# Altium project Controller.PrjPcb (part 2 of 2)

## Sheet Auxiliary Power.SchDoc: 60KW GMA DAB (CONTROL) - AUXILIARY POWER
size 431 x 279 mm; Date: 11/2023; Revision: 1.0; SheetNumber: 5; SheetTotal: 5; SheetSize: B; DrawingNumber: CRD60DD12N-GMA-CONTROL
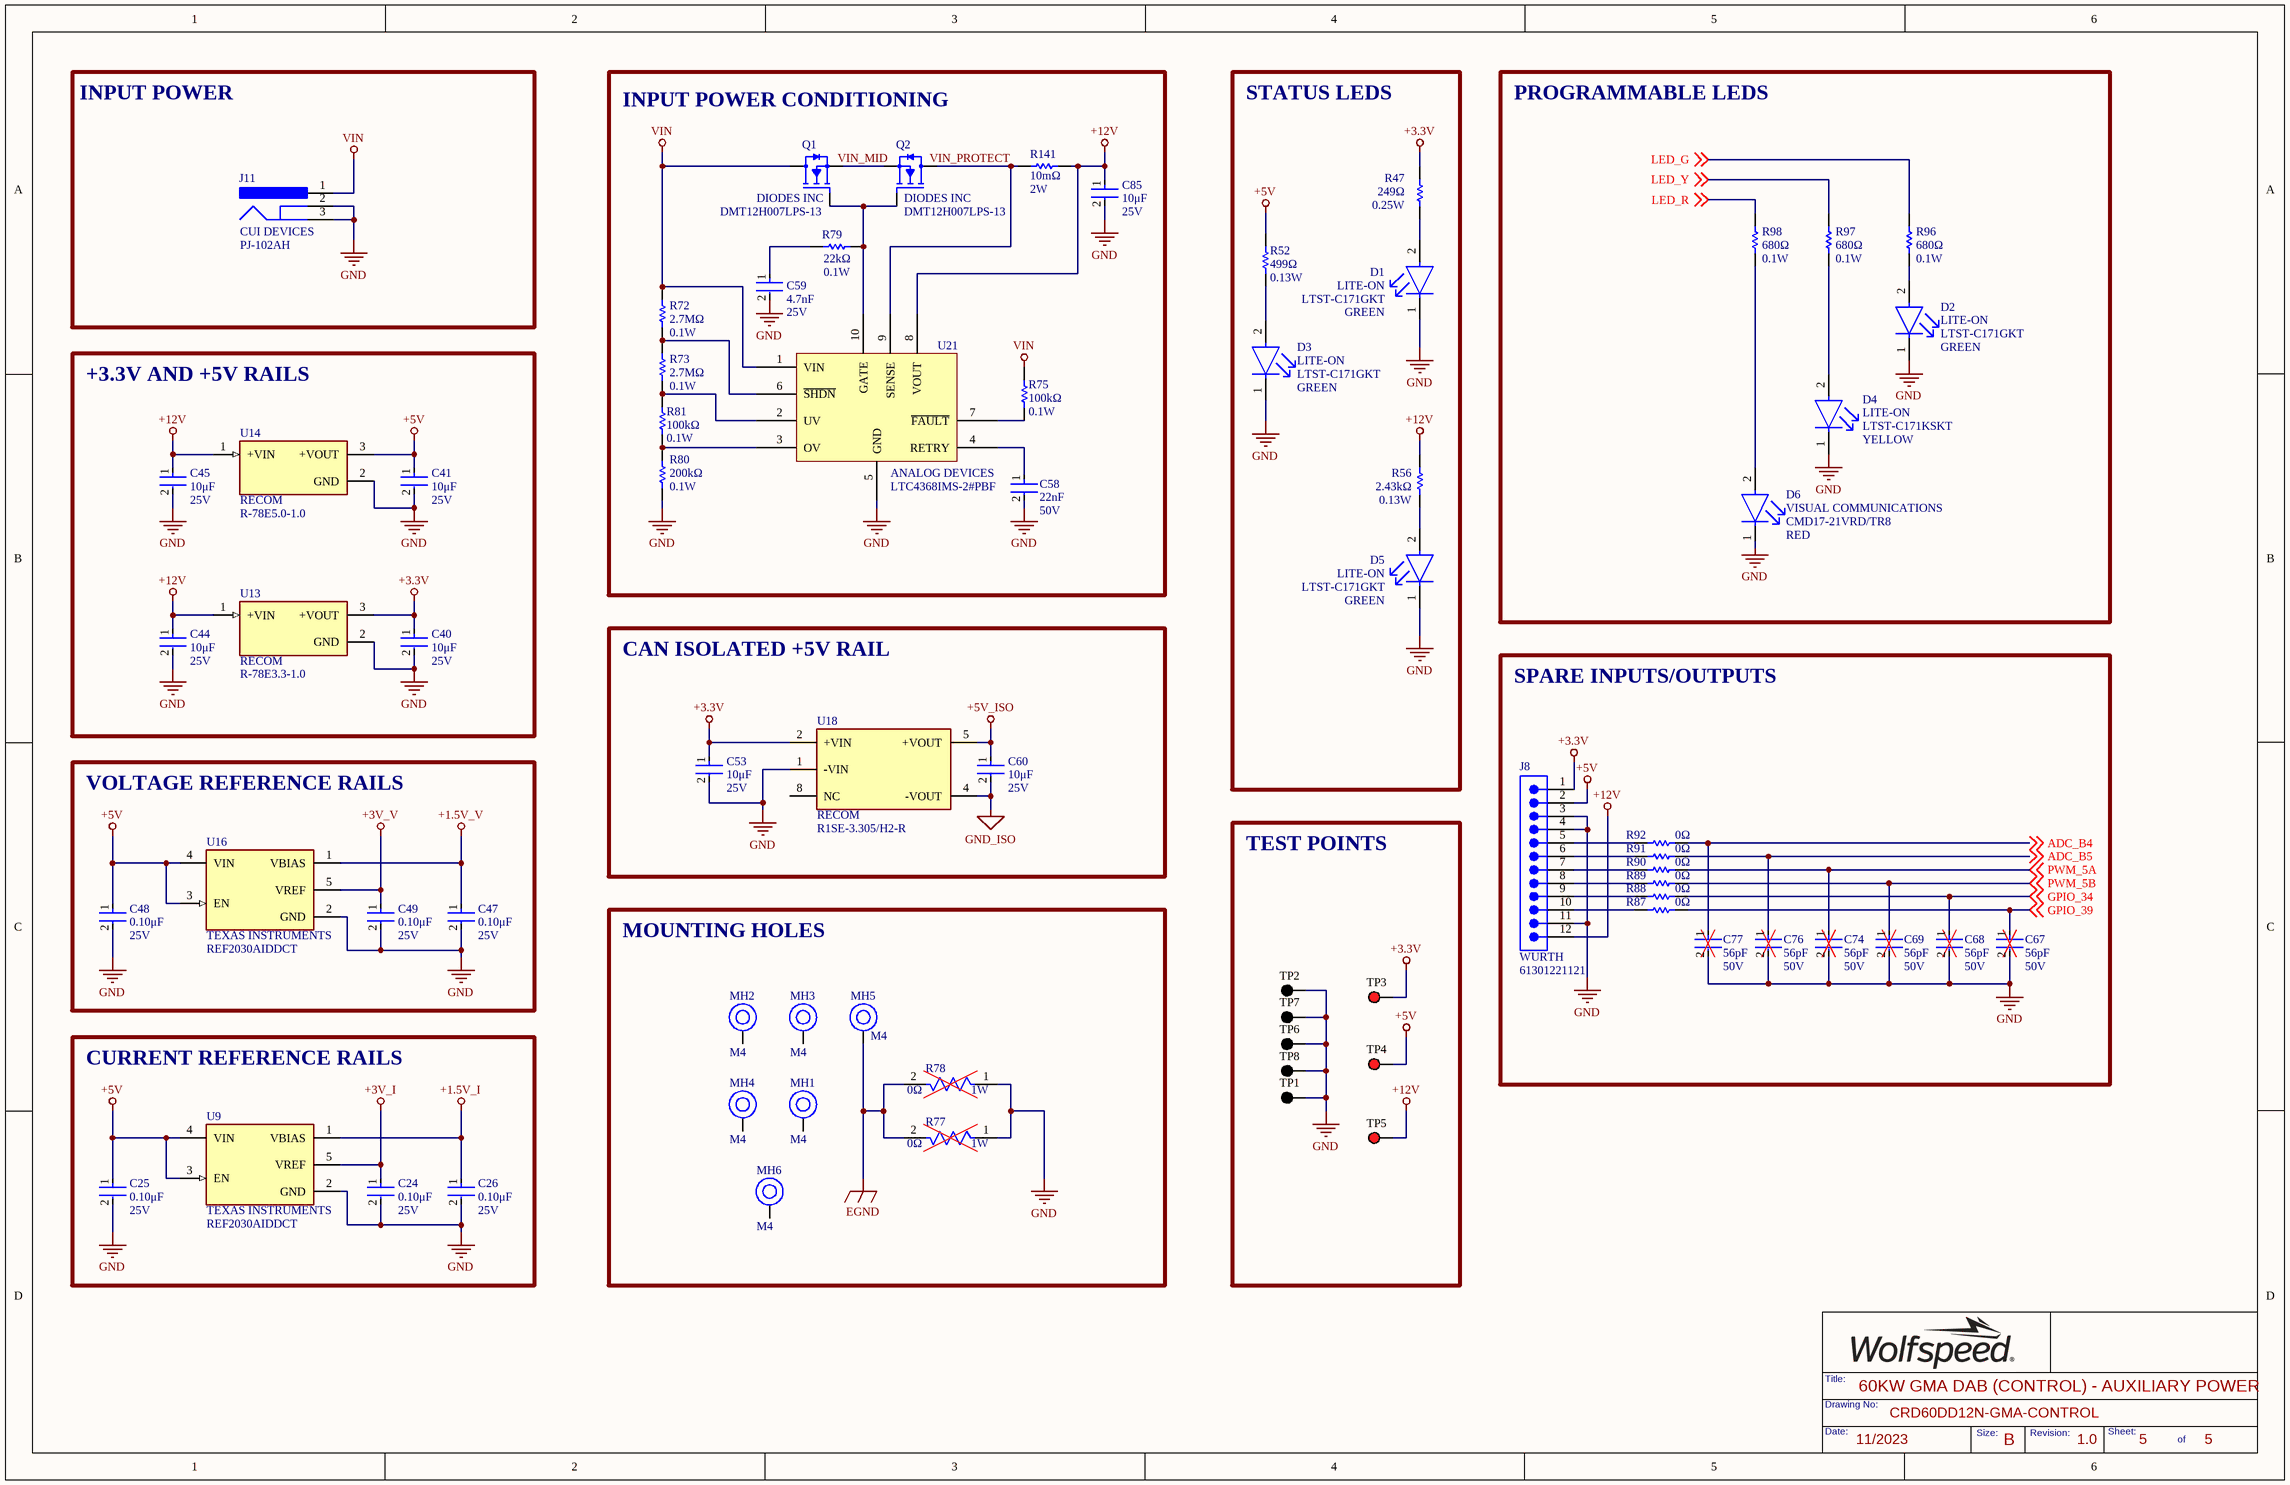
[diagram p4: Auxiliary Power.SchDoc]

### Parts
C24  Voltage Rating: 25V  Capacitance: 0.10μF  [FP-C0603C-CF-IPC_B]  (hidden comment: C0603C104K3RACTU)
C25  Voltage Rating: 25V  Capacitance: 0.10μF  [FP-C0603C-CF-IPC_B]  (hidden comment: C0603C104K3RACTU)
C26  Voltage Rating: 25V  Capacitance: 0.10μF  [FP-C0603C-CF-IPC_B]  (hidden comment: C0603C104K3RACTU)
C40  Voltage Rating: 25V  Capacitance: 10μF  [FP-CL31-IPC_B]  (hidden comment: CL31B106KAHSFNE)
C41  Voltage Rating: 25V  Capacitance: 10μF  [FP-CL31-IPC_B]  (hidden comment: CL31B106KAHSFNE)
C44  Voltage Rating: 25V  Capacitance: 10μF  [FP-CL31-IPC_B]  (hidden comment: CL31B106KAHSFNE)
C45  Voltage Rating: 25V  Capacitance: 10μF  [FP-CL31-IPC_B]  (hidden comment: CL31B106KAHSFNE)
C47  Voltage Rating: 25V  Capacitance: 0.10μF  [FP-C0603C-CF-IPC_B]  (hidden comment: C0603C104K3RACTU)
C48  Voltage Rating: 25V  Capacitance: 0.10μF  [FP-C0603C-CF-IPC_B]  (hidden comment: C0603C104K3RACTU)
C49  Voltage Rating: 25V  Capacitance: 0.10μF  [FP-C0603C-CF-IPC_B]  (hidden comment: C0603C104K3RACTU)
C53  Voltage Rating: 25V  Capacitance: 10μF  [FP-CL31-IPC_B]  (hidden comment: CL31B106KAHSFNE)
C58  Capacitance: 22nF  Voltage: 50V  [FP-C0603C-CF-IPC_B]  (hidden comment: CC0805KRX7R9BB223)
C59  Voltage Rating: 25V  Capacitance: 4.7nF  [FP-C0603C-CF-IPC_B]  (hidden comment: C0603C472K3RAC7867)
C60  Voltage Rating: 25V  Capacitance: 10μF  [FP-CL31-IPC_B]  (hidden comment: CL31B106KAHSFNE)
C67  Capacitance: 56pF  Voltage Rating: 50V  [FP-C0603C-CF-IPC_B]  (hidden comment: CL10C560JB8NNNC)
C68  Capacitance: 56pF  Voltage Rating: 50V  [FP-C0603C-CF-IPC_B]  (hidden comment: CL10C560JB8NNNC)
C69  Capacitance: 56pF  Voltage Rating: 50V  [FP-C0603C-CF-IPC_B]  (hidden comment: CL10C560JB8NNNC)
C74  Capacitance: 56pF  Voltage Rating: 50V  [FP-C0603C-CF-IPC_B]  (hidden comment: CL10C560JB8NNNC)
C76  Capacitance: 56pF  Voltage Rating: 50V  [FP-C0603C-CF-IPC_B]  (hidden comment: CL10C560JB8NNNC)
C77  Capacitance: 56pF  Voltage Rating: 50V  [FP-C0603C-CF-IPC_B]  (hidden comment: CL10C560JB8NNNC)
C85  Voltage Rating: 25V  Capacitance: 10μF  [FP-CL31-IPC_B]  (hidden comment: CL31B106KAHSFNE)
D1  value GREEN  Manufacturer: LITE-ON  [FP-LTST-C171GKT-MFG]  (hidden comment: LTST-C171GKT)
D2  value GREEN  Manufacturer: LITE-ON  [FP-LTST-C171GKT-MFG]  (hidden comment: LTST-C171GKT)
D3  value GREEN  Manufacturer: LITE-ON  [FP-LTST-C171GKT-MFG]  (hidden comment: LTST-C171GKT)
D4  LTST-C171KSKT  value YELLOW  Manufacturer: LITE-ON  [FP-LTST-C171GKT-MFG-YELLOW]
D5  value GREEN  Manufacturer: LITE-ON  [FP-LTST-C171GKT-MFG]  (hidden comment: LTST-C171GKT)
D6  value RED  Manufacturer: VISUAL COMMUNICATIONS  [FP-LTST-C171GKT-MFG-RED]  (hidden comment: CMD17-21VRD/TR8)
J8  Manufacturer Print: WURTH  [FP-61301221121-MFG]  (hidden comment: 61301221121)
J11  PJ-102AH  Manufacturer Print: CUI DEVICES  [CUI-PJ-102B_V]
MH1  Size: M4  [MH_M4_P]  (hidden comment: MH_M4_P)
MH2  Size: M4  [MH_M4_P]  (hidden comment: MH_M4_P)
MH3  Size: M4  [MH_M4_P]  (hidden comment: MH_M4_P)
MH4  Size: M4  [MH_M4_P]  (hidden comment: MH_M4_P)
MH5  Size: M4  [MH_M4_P]  (hidden comment: MH_M4_P)
MH6  Size: M4  [MH_M4_P]  (hidden comment: MH_M4_P)
Q1  DMT12H007LPS-13  Manufacturer: DIODES INC  [FP-PowerDI5060-8-MFG]
Q2  DMT12H007LPS-13  Manufacturer: DIODES INC  [FP-PowerDI5060-8-MFG]
R47  Resistance: 249Ω  Power Rating: 0.25W  [FP-MCR18-IPC_A]  (hidden comment: RC1206FR-07249RL)
R52  Resistance: 499Ω  Max Power Dissipation: 0.13W  [FP-MCR10-IPC_A]  (hidden comment: RC0805FR-07499RL)
R56  Resistance: 2.43kΩ  Power Rating: 0.13W  [FP-MCR10-IPC_A]  (hidden comment: ERJ-6ENF2431V)
R72  Power Rating: 0.1W  Resistance: 2.7MΩ  [FP-MCR03-IPC_B]  (hidden comment: RC0603JR-072M7L)
R73  Power Rating: 0.1W  Resistance: 2.7MΩ  [FP-MCR03-IPC_B]  (hidden comment: RC0603JR-072M7L)
R75  Resistance: 100kΩ  Power Rating: 0.1W  [FP-MCR03-IPC_B]  (hidden comment: RC0603FR-07100KL)
R77  value 0Ω  Max Power Dissipation: 1W  [FP-RC2512-0_65-IPC_C]  (hidden comment: RC2512JK-070RL)
R78  value 0Ω  Max Power Dissipation: 1W  [FP-RC2512-0_65-IPC_C]  (hidden comment: RC2512JK-070RL)
R79  Power Rating: 0.1W  Resistance: 22kΩ  [FP-MCR03-IPC_B]  (hidden comment: ERJ-3EKF2202V)
R80  Resistance: 200kΩ  Max Power Dissipation: 0.1W  [FP-MCR03-IPC_B]  (hidden comment: ERJ-3EKF2003V)
R81  Resistance: 100kΩ  Power Rating: 0.1W  [FP-MCR03-IPC_B]  (hidden comment: RC0603FR-07100KL)
R87  Resistance: 0Ω  [FP-MCR03-IPC_B]  (hidden comment: CRCW06030000Z0EB)
R88  Resistance: 0Ω  [FP-MCR03-IPC_B]  (hidden comment: CRCW06030000Z0EB)
R89  Resistance: 0Ω  [FP-MCR03-IPC_B]  (hidden comment: CRCW06030000Z0EB)
R90  Resistance: 0Ω  [FP-MCR03-IPC_B]  (hidden comment: CRCW06030000Z0EB)
R91  Resistance: 0Ω  [FP-MCR03-IPC_B]  (hidden comment: CRCW06030000Z0EB)
R92  Resistance: 0Ω  [FP-MCR03-IPC_B]  (hidden comment: CRCW06030000Z0EB)
R96  Power Rating: 0.1W  Resistance: 680Ω  [FP-MCR03-IPC_B]  (hidden comment: RC0603FR-07680RL)
R97  Power Rating: 0.1W  Resistance: 680Ω  [FP-MCR03-IPC_B]  (hidden comment: RC0603FR-07680RL)
R98  Power Rating: 0.1W  Resistance: 680Ω  [FP-MCR03-IPC_B]  (hidden comment: RC0603FR-07680RL)
R141  Resistance: 10mΩ  Max Power Dissipation: 2W  [FP-RL2512-IPC_A]  (hidden comment: PE2512FKE7W0R01L)
TP1  5011  [KSTN-5011_V]  (value not drawn)
TP2  5011  [KSTN-5011_V]  (value not drawn)
TP3  5010  [KSTN-5010_V]  (value not drawn)
TP4  5010  [KSTN-5010_V]  (value not drawn)
TP5  5010  [KSTN-5010_V]  (value not drawn)
TP6  5011  [KSTN-5011_V]  (value not drawn)
TP7  5011  [KSTN-5011_V]  (value not drawn)
TP8  5011  [KSTN-5011_V]  (value not drawn)
U9  REF2030AIDDCT  Manufacturer: TEXAS INSTRUMENTS  [FP-DDC0005A-MFG]
U13  R-78E3.3-1.0  Manufacturer Print: RECOM  [CONV_R-78E3.3-1.0]
U14  R-78E5.0-1.0  Manufacturer Print: RECOM  [CONV_R-78E5.0-1.0]
U16  REF2030AIDDCT  Manufacturer: TEXAS INSTRUMENTS  [FP-DDC0005A-MFG]
U18  Manufacturer: RECOM  [FP-R1SE-0505-R-MFG]  (hidden comment: R1SE-3.305/H2-R)
U21  LTC4368IMS-2#PBF  Manufacturer Print: ANALOG DEVICES  [SOP50P490X110-10N]

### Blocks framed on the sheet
INPUT POWER: J11
INPUT POWER CONDITIONING: C58 C59 C85 Q1 Q2 R72 R73 R75 R79-R81 R141 U21
STATUS LEDS: D1 D3 D5 R47 R52 R56
PROGRAMMABLE LEDS: D2 D4 D6 R96-R98
+3.3V AND +5V RAILS: C40 C41 C44 C45 U13 U14
CAN ISOLATED +5V RAIL: C53 C60 U18
SPARE INPUTS/OUTPUTS: C67-C69 C74 C76 C77 J8 R87-R92
VOLTAGE REFERENCE RAILS: C47-C49 U16
TEST POINTS: TP1-TP8
MOUNTING HOLES: MH1-MH6 R77 R78
CURRENT REFERENCE RAILS: C24-C26 U9

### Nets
+1.5V_I: C26.1 U9.1(VBIAS)
+1.5V_V: C47.1 U16.1(VBIAS)
+3.3V: C40.1 C53.1 J8.1 R47.1 TP3.1 U13.3(+VOUT) U18.2(+VIN)
+3V_I: C24.1 U9.5(VREF)
+3V_V: C49.1 U16.5(VREF)
+5V: C25.1 C41.1 C48.1 J8.2 R52.2 TP4.1 U9.3(EN) U9.4(VIN) U14.3(+VOUT) U16.3(EN) U16.4(VIN)
+5V_ISO: C60.1 U18.5(+VOUT)
+12V: C44.1 C45.1 C85.1 J8.12 R56.2 R141.2 TP5.1 U13.1(+VIN) U14.1(+VIN) U21.8(VOUT)
EGND: MH5.1 R77.2 R78.2
GND: C24.2 C25.2 C26.2 C40.2 C41.2 C44.2 C45.2 C47.2 C48.2 C49.2 C53.2 C58.2 C59.2 C67.2 C68.2 C69.2 C74.2 C76.2 C77.2 C85.2 D1.1(C) D2.1(C) D3.1(C) D4.1(C) D5.1(C) D6.1(C) J8.3 J8.4 J8.11 J11.2 J11.3 R77.1 R78.1 R80.1 TP1.1 TP2.1 TP6.1 TP7.1 TP8.1 U9.2(GND) U13.2(GND) U14.2(GND) U16.2(GND) U18.1(-VIN) U21.5(GND)
GND_ISO: C60.2 U18.4(-VOUT)
VIN: J11.1 Q1.5(D) R72.2 R75.2 U21.1(VIN)
ADC_B4: C77.1 R92.2 ; off-sheet ADC_B4
ADC_B5: C76.1 R91.2 ; off-sheet ADC_B5
GPIO_34: C68.1 R88.2 ; off-sheet GPIO_34
GPIO_39: C67.1 R87.2 ; off-sheet GPIO_39
LED_G: R96.2 ; off-sheet LED_G
LED_R: R98.2 ; off-sheet LED_R
LED_Y: R97.2 ; off-sheet LED_Y
PWM_5A: C74.1 R90.2 ; off-sheet PWM_5A
PWM_5B: C69.1 R89.2 ; off-sheet PWM_5B
VIN_MID: Q1.1,2,3(S) Q2.1,2,3(S)
VIN_PROTECT: Q2.5(D) R141.1 U21.9(SENSE)
NetC58_1: C58.1 U21.4(RETRY)
NetC59_1: C59.1 R79.1
NetD1_2: D1.2(A) R47.2
NetD2_2: D2.2(A) R96.1
NetD3_2: D3.2(A) R52.1
NetD4_2: D4.2(A) R97.1
NetD5_2: D5.2(A) R56.1
NetD6_2: D6.2(A) R98.1
NetJ8_5: J8.5 R92.1
NetJ8_6: J8.6 R91.1
NetJ8_7: J8.7 R90.1
NetJ8_8: J8.8 R89.1
NetJ8_9: J8.9 R88.1
NetJ8_10: J8.10 R87.1
NetQ1_4: Q1.4(G) Q2.4(G) R79.2 U21.10(GATE)
NetR72_1: R72.1 R73.2 U21.6(~{SHDN})
NetR73_1: R73.1 R81.2 U21.2(UV)
NetR75_1: R75.1 U21.7(~{FAULT})
NetR80_2: R80.2 R81.1 U21.3(OV)

Not connected (* = marked no-connect by the designer): MH1 1; MH2 1; MH3 1; MH4 1; MH6 1; U18 8(NC)

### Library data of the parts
C24-C26 C47-C49 = CMP-2006-03057-2: CAP CER 0.1UF 25V X7R 0603; Manufacturer: KEMET; Value: 0.10μF; Material: Ceramic; Tolerance: 0.1; Temperature Coefficient: 30ppm/°C; Automotive Grade: Grade 1
C40 C41 C44 C45 C53 C60 C85 = CMP-13271-001434-1: CAP CER 10UF 25V X7R 1206; Manufacturer: SAMSUNG; Tolerance: 10%; Value: 10μF
C58 = CC0805KRX7R9BB223: CAP CER 0.022UF 50V X7R 0805; Manufacturer: YAGEO; Material: Ceramic; Tolerance: 10%; Insulation Resistance: 100GR; Value: 22nF
C59 = C0603C472K3RAC7867: CAP CER 4700PF 25V 10% X7R 0603; Manufacturer: KEMET; Manufacturer Part Number: C0603C472K3RACTU; Dielectric Material: Ceramic; Value: 4.7nF
C67-C69 C74 C76 C77 = CL10C560JB8NNNC: CAP CER 56PF 50V C0G/NP0 0603; Manufacturer: SAMSUNG; Material: Ceramic; Tolerance: 5%; Dielectric: C0G; Temperature Coefficient: 30ppm/°C
D1-D3 D5 = CMP-22017-000007-1: LED GREEN CLEAR CHIP SMD; Luminous Intensity: 12mcd; Lens Color: Colorless; Dominant Wavelength: 569nm; Number of LEDs: 1; Power Dissipation: 100mW; Viewing Angle: 130°; Reverse Voltage: 5V; Test Current: 10mA; Forward Voltage: 2.1V; Wavelength: 585nm; Lens Style: Diffused; Forward Current: 30mA
D4 = LTST-C171KSKT: LED YELLOW CLEAR 0805 SMD; Lens Color: Colorless; Number of LEDs: 1; Reverse Voltage: 5V; Viewing Angle: 130°; Lens Style: Diffused,Colorless,Rectangular,Clear; Luminous Intensity: 50mcd; Forward Voltage: 2V; Dominant Wavelength: 587nm; Test Current: 20mA; Wavelength: 588nm; Forward Current: 30mA; Max Power Dissipation: 75mW
D6 = CMD17-21VRD/TR8: LED RED DIFFUSED 0805 SMD; Power Rating: 100mW; Luminous Intensity: 6mcd; Viewing Angle: 140°; Lens Style: Diffused,Tinted,Rectangular,Colored; Forward Current: 20mA; Forward Voltage: 2V; Wavelength: 640nm; Reverse Voltage (DC): 5V; Number of LEDs: 1
J8 = 61301221121: CONN HEADER VERT 12POS 2.54MM; Manufacturer: WURTH ELEKTRONIK; Number of Positions: 12; Gender: Male; Voltage Rating: 250V; Pitch: 0.1inch
J11 = PJ-102AH: CONN PWR JACK 2X5.5MM SOLDER; Manufacturer: CUI; Gender: Male; Shielding: Unshielded; Current Rating: 5A; Voltage Rating: 24V; Insulation Resistance: 50MR; Number of Conductors: 2
Q1 Q2 = DMT12H007LPS-13: MOSFET N-CH 120V 90A PWRDI5060-8
R47 = RC1206FR-07249RL: RES 249 OHM 1% 1/4W 1206; Manufacturer: YAGEO; Voltage Rating: 200V; Temperature Coefficient: 100ppm/°C; Max Power Dissipation: 250mW; Value: 249Ω
R52 = RC0805FR-07499RL: RES 499 OHM 1% 1/8W 0805; Manufacturer: YAGEO; Power Rating: 125mW; Voltage Rating: 150V; Temperature Coefficient: 100ppm/°C; Value: 499Ω
R56 = ERJ-6ENF2431V: RES SMD 2.43K OHM 1% 1/8W 0805; Manufacturer: PANASONIC; Temperature Coefficient: 100ppm/°C; Voltage Rating: 150V; Max Power Dissipation: 125mW; Value: 2.43kΩ
R72 R73 = RC0603JR-072M7L: RES 2.7M OHM 5% 1/10W 0603; Manufacturer: YAGEO; Temperature Coefficient: 100ppm/°C; Voltage Rating: 75V; Max Power Dissipation: 100mW; Voltage Rating (DC): 50V; Value: 2.7MΩ
R75 R81 = RC0603FR-07100KL: RES 100K OHM 1% 1/10W 0603; Manufacturer: YAGEO; Temperature Coefficient: 100ppm/°C; Voltage Rating: 50V; Working Voltage: 75V; Max Power Dissipation: 100mW; Value: 100kΩ
R77 R78 = CMP-2000-06974-2: RES SMD 0 OHM JUMPER 1W 2512; Manufacturer: YAGEO; Tolerance: 5%; Voltage Rating: 200V; Temperature Coefficient: 200ppm/°C
R79 = CMP-2000-00337-2: RES SMD 22K OHM 1% 1/10W 0603; Manufacturer: PANASONIC; Voltage Rating: 50 V; Value: 22kΩ
R80 = ERJ-3EKF2003V: RES SMD 200K OHM 1% 1/10W 0603; Manufacturer: PANASONIC; Temperature Coefficient: 100ppm/°C; Power Rating: 100mW; Voltage Rating: 75V; Voltage Rating (DC): 50V; Value: 200kΩ
R87-R92 = CRCW06030000Z0EB: RES SMD 0 OHM JUMPER 1/10W 0603; Manufacturer: VISHAY DALE; Manufacturer Part Number: CRCW06030000Z0EBC; Max Power Dissipation: 100mW; Voltage Rating: 75V; Tolerance: 1%; Temperature Coefficient: 100ppm/°C; Value: 0Ω
R96-R98 = RC0603FR-07680RL: RES 680 OHM 1% 1/10W 0603; Manufacturer: YAGEO; Voltage Rating (DC): 50V; Temperature Coefficient: 100ppm/°C; Max Power Dissipation: 100mW; Value: 680Ω
R141 = PE2512FKE7W0R01L: RES 0.01 OHM 1% 2W 2512; Manufacturer: YAGEO; Temperature Coefficient: 50ppm/°C; Value: 10mΩ
TP1 TP2 TP6-TP8 = CMP-1672-00003-4: PC TEST POINT MULTIPURPOSE BLACK; Manufacturer: KEYSTONE
TP3-TP5 = CMP-1672-00002-4: PC TEST POINT MULTIPURPOSE RED; Manufacturer: KEYSTONE
U9 U16 = CMP-04916-000006-1: IC VREF SERIES 1.5V/3V 5SOT; Output Type: Fixed; Nominal Supply Current: 360uA; Number Of Outputs: 1; Standoff Height: 0mm; Max Junction Temp: +150°C; Output Voltage: 1.5/3V; Max Supply Voltage: 5.5V; Min Supply Voltage: 3V
U13 = R-78E3.3-1.0: DC DC CONVERTER 3.3V 3W; Number of Outputs: 1; Min Input Voltage: 8V; Max Input Voltage: 28V; Max Output Current: 1A; Efficiency: 91%; Max Output Power: 3.3W; Min Input Voltage (DC): 7V
U14 = R-78E5.0-1.0: DC DC CONVERTER 5V 5W; Number of Outputs: 1; Min Input Voltage: 8V; Max Input Voltage: 28V; Max Output Current: 1A; Efficiency: 91%
U18 = R1SE-3.305/H2-R: DC DC CONVERTER 5V 1W; Number of Outputs: 1; Min Input Voltage: 2.97V; Max Input Voltage: 3.63V; Max Output Current: 200mA; Isolation Voltage: 2kV; Efficiency: 75%
U21 = LTC4368IMS-2#PBF: IC SURGE SUPPRESSION ADJ 10MSOP

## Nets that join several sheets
+1.5V_V: Voltage Sense (R64.2 R74.2), Auxiliary Power (C47.1 U16.1)
+3.3V: Controller (C54.1 U19.1), Voltage Sense (8 pins), Gate Drivers (16 pins), Auxiliary Power (7 pins)
+3V_I: Current Sense (R22.2 R34.2 R46.2), Auxiliary Power (C24.1 U9.5)
+5V: Controller (13 pins), Current Sense (15 pins), Auxiliary Power (11 pins)
+5V_ISO: Controller (C61.1 J12.9 U19.8), Auxiliary Power (C60.1 U18.5)
+12V: Gate Drivers (J1.1 J2.1 J3.1 J4.1), Auxiliary Power (10 pins)
GND: Controller (26 pins), Voltage Sense (18 pins), Gate Drivers (48 pins), Current Sense (39 pins), Auxiliary Power (45 pins)
GND_ISO: Controller (5 pins), Auxiliary Power (C60.2 U18.4)
ADC_B4: Controller (U1.24), Auxiliary Power (C77.1 R92.2)
ADC_B5: Controller (U1.26), Auxiliary Power (C76.1 R91.2)
GPIO_34: Controller (U1.86), Auxiliary Power (C68.1 R88.2)
GPIO_39: Controller (U1.88), Auxiliary Power (C67.1 R87.2)
I_DC: Controller (U1.18), Current Sense (C78.1 R93.2)
I_IN: Controller (U1.12), Current Sense (C84.1 R95.2)
I_OUT: Controller (U1.14), Current Sense (C81.1 R94.2)
INA_FLT: Controller (U1.121), Gate Drivers (U4.3)
INA_HS: Controller (U1.49), Gate Drivers (R19.1)
INA_LEN_CTRL: Controller (U1.144), Gate Drivers (U5.5)
INA_LS: Controller (U1.51), Gate Drivers (R18.1)
INA_NTC: Controller (U1.58), Gate Drivers (U4.13)
INA_OCEN_CTRL: Controller (U1.146), Gate Drivers (U5.6)
INA_PSDIS_CTRL: Controller (U1.142), Gate Drivers (U5.4)
INB_FLT: Controller (U1.122), Gate Drivers (U4.11)
INB_HS: Controller (U1.53), Gate Drivers (R17.1)
INB_LEN_CTRL: Controller (U1.152), Gate Drivers (U5.8)
INB_LS: Controller (U1.55), Gate Drivers (R16.1)
INB_NTC: Controller (U1.60), Gate Drivers (U4.5)
INB_OCEN_CTRL: Controller (U1.154), Gate Drivers (U5.9)
INB_PSDIS_CTRL: Controller (U1.150), Gate Drivers (U5.7)
LED_G: Controller (U1.108), Auxiliary Power (R96.2)
LED_R: Controller (U1.126), Auxiliary Power (R98.2)
LED_Y: Controller (U1.110), Auxiliary Power (R97.2)
OUTA_FLT: Controller (U1.123), Gate Drivers (U2.3)
OUTA_HS: Controller (U1.50), Gate Drivers (R83.1)
OUTA_LEN_CTRL: Controller (U1.145), Gate Drivers (U3.5)
OUTA_LS: Controller (U1.52), Gate Drivers (R84.1)
OUTA_NTC: Controller (U1.62), Gate Drivers (U2.13)
OUTA_OCEN_CTRL: Controller (U1.147), Gate Drivers (U3.6)
OUTA_PSDIS_CTRL: Controller (U1.143), Gate Drivers (U3.4)
OUTB_FLT: Controller (U1.124), Gate Drivers (U2.11)
OUTB_HS: Controller (U1.54), Gate Drivers (R85.1)
OUTB_LEN_CTRL: Controller (U1.153), Gate Drivers (U3.8)
OUTB_LS: Controller (U1.56), Gate Drivers (R86.1)
OUTB_NTC: Controller (U1.64), Gate Drivers (U2.5)
OUTB_OCEN_CTRL: Controller (U1.155), Gate Drivers (U3.9)
OUTB_PSDIS_CTRL: Controller (U1.151), Gate Drivers (U3.7)
PWM_5A: Controller (U1.57), Auxiliary Power (C74.1 R90.2)
PWM_5B: Controller (U1.59), Auxiliary Power (C69.1 R89.2)
VAC_IN: Controller (U1.9), Voltage Sense (C83.1 R39.2)
VAC_OUT: Controller (U1.15), Voltage Sense (C80.1 R32.2)
VDC_IN: Controller (U1.11), Voltage Sense (C82.1 R35.2)
VDC_OUT: Controller (U1.17), Voltage Sense (C79.1 R31.2)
